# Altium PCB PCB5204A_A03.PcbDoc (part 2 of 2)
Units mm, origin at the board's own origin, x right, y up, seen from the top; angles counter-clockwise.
Board outline 38.5 x 55.5 mm, 4 copper layers (Top Layer, Signal Layer 2, Signal Layer 3, Bottom Layer), stack 1.6 mm thick; 164 components, 105 nets, 579 pads, 390 vias.
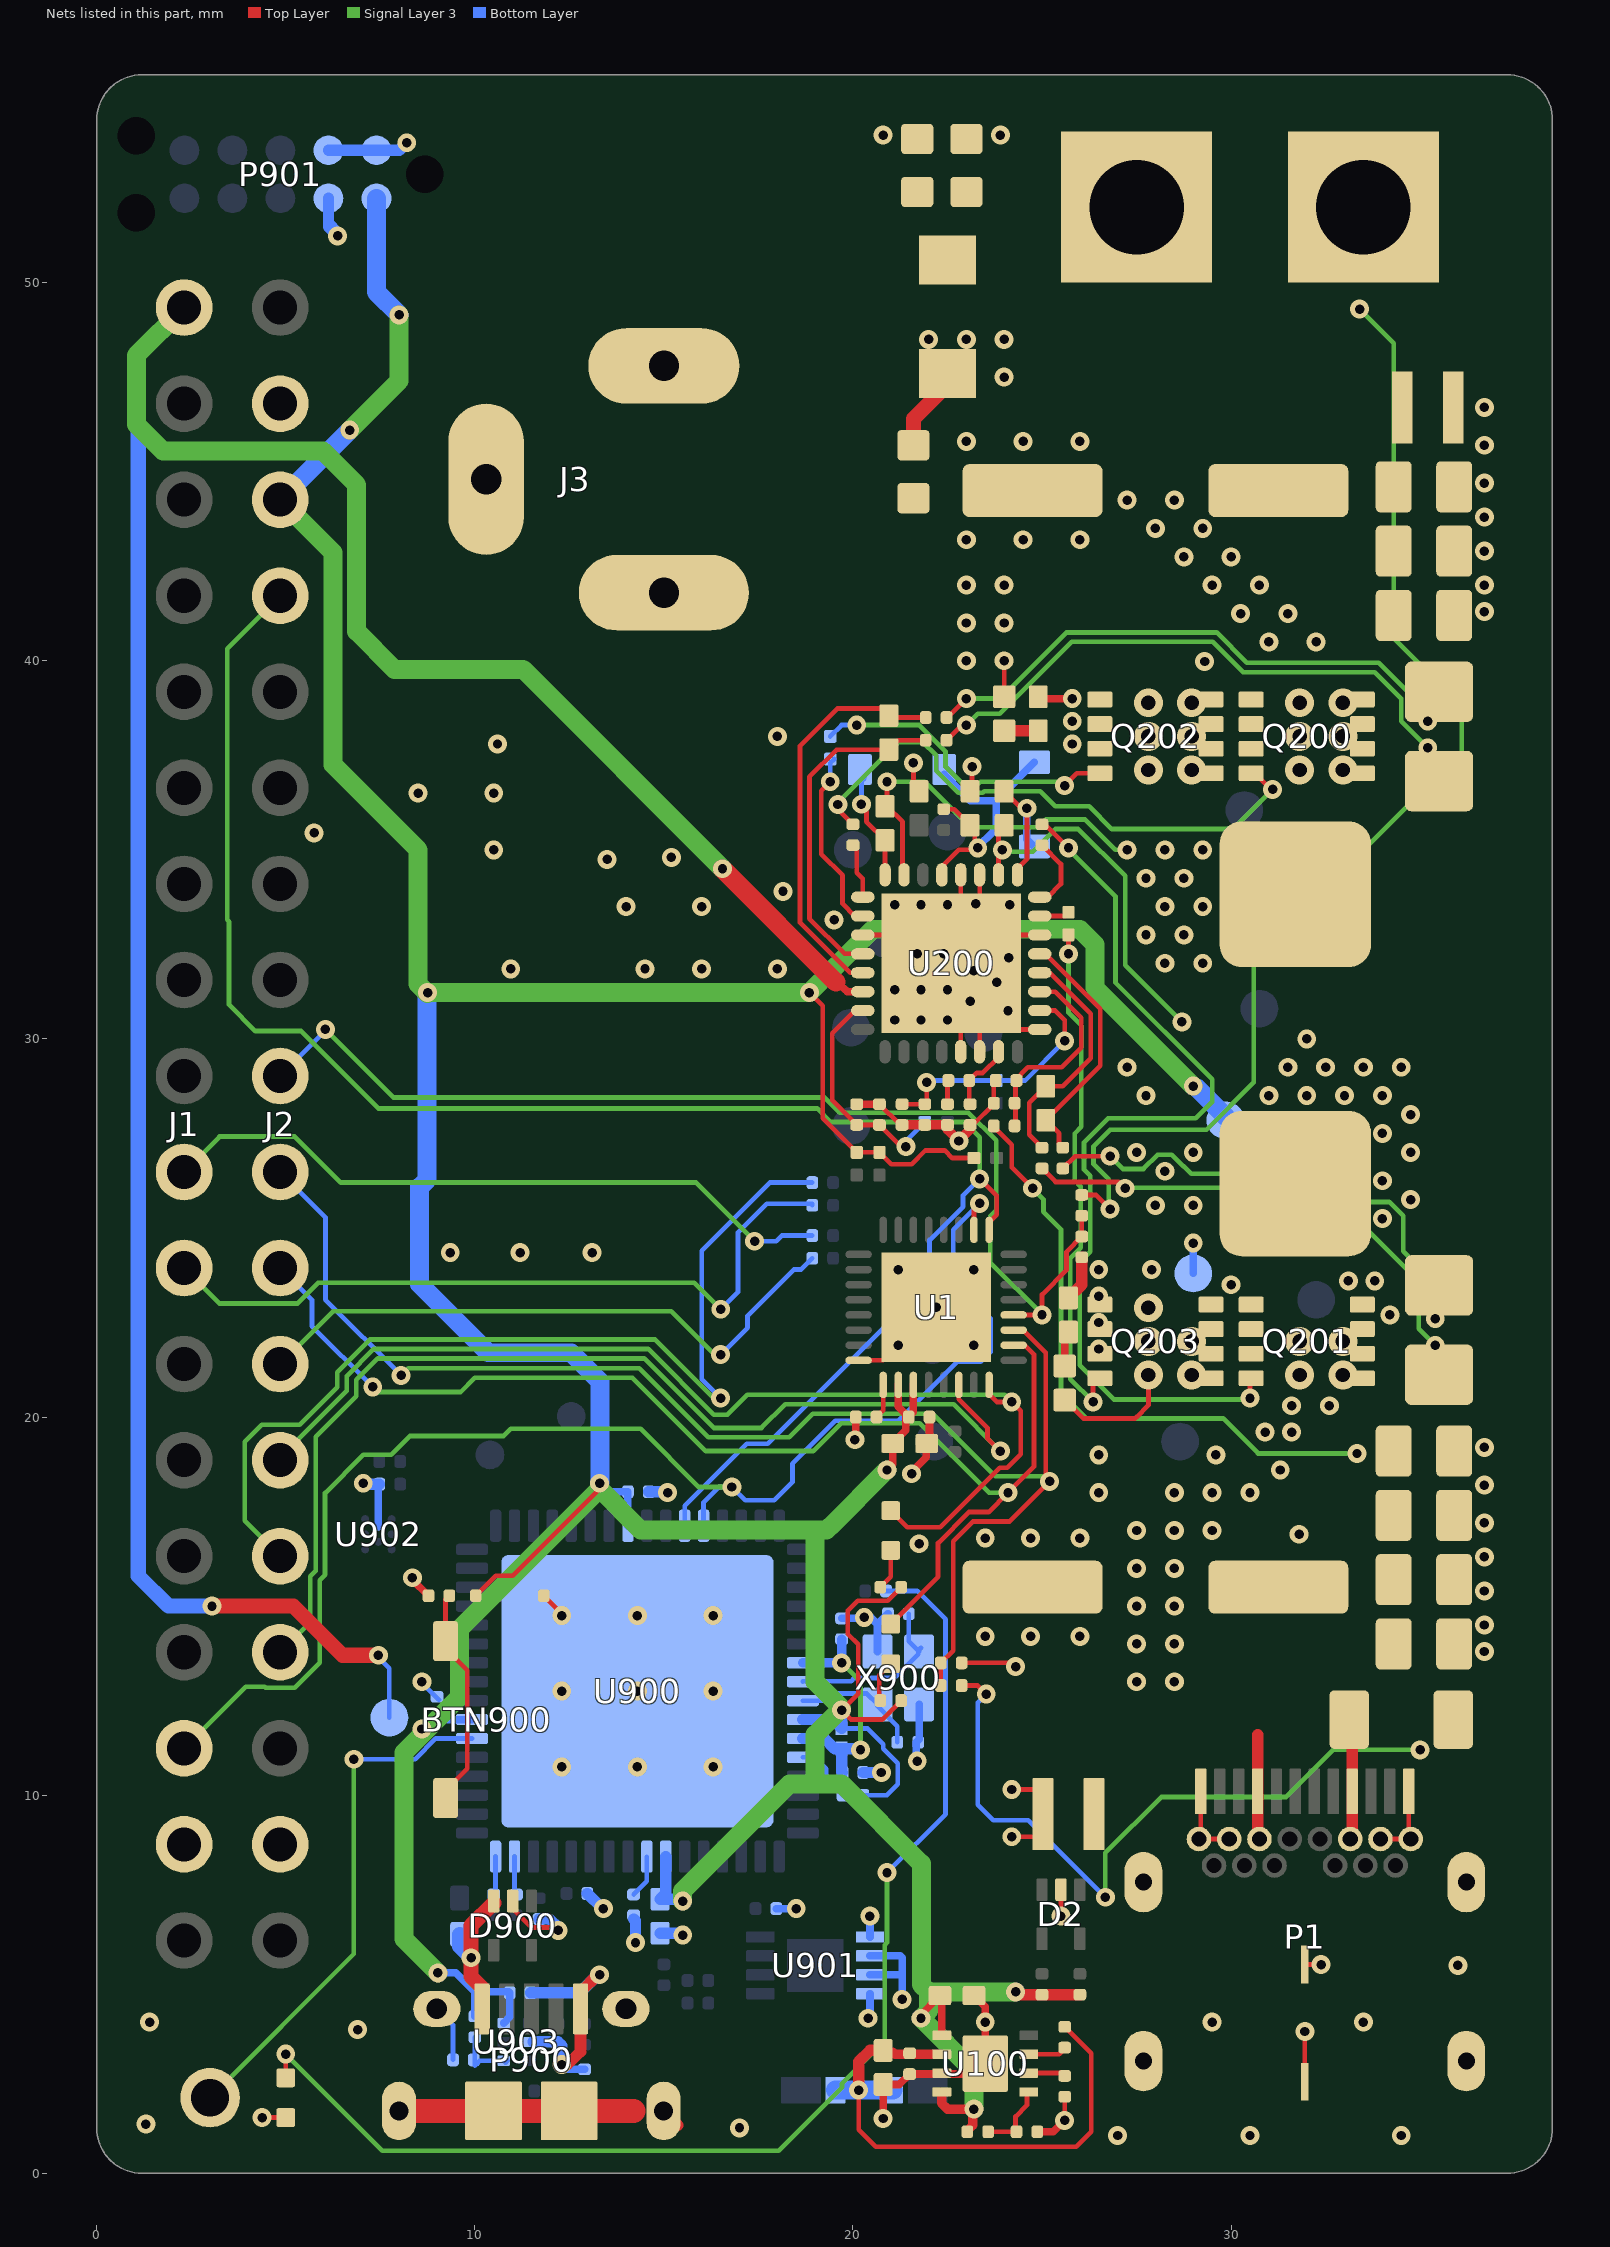
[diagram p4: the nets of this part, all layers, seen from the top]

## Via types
v1: diameter 0.5, hole 0.25, Top Layer to Bottom Layer, tented both sides, 369 vias
v2: diameter 0.762, hole 0.381, Top Layer to Bottom Layer, tented both sides, 21 vias

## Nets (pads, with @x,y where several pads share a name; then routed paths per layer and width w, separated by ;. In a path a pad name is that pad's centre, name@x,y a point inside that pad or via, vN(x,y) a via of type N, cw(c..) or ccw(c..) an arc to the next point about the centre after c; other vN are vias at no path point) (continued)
EFM8_P2.5: J2.9 R1.2 R2.2 U1.12 | length 29.9
  Top Layer w0.125: U1.12@24.25,22.7 24.975,22.7 v1@25,22.725 ; v1(25,22.7) v1@25,22.725 ; R1.2@26.05,25.325 R2.2@26.05,24.775 25.65,24.375 25.65,23.89 25,23.24 v1@25,22.725
  Signal Layer 3 w0.125: J2.9@4.853,29.02 J2.9@4.973,28.9 ; v1(6.05,30.25) 7.85,28.45 19.25,28.45 19.65,28.05 23.054,28.05 23.788,27.316 23.788,25.469 23.634,25.316 23.634,24.084 25,22.719 v1(25,22.7)
  Bottom Layer w0.125: J2.9@4.853,29.02 6.05,30.217 v1(6.05,30.25)
EFM8_P2.6: J2.10 R3.1 R4.2 U1.11 | length 37.4
  Top Layer w0.125: R3.1@22.325,12.9 R4.2@22.325,13.5 22.65,13.825 22.65,16.715 23.172,17.238 24.138,17.238 v1(25.2,18.3) 25.1,18.4 25.1,21.707 24.507,22.3 U1.11@24.25,22.3
  Signal Layer 3 w0.125: v1(8.05,21.1) 8.238,21.288 14.35,21.288 16.175,19.462 18.312,19.462 18.938,20.088 22.112,20.088 23.763,18.438 25.062,18.438 v1(25.2,18.3)
  Bottom Layer w0.125: J2.10@4.853,26.48 6.05,25.283 6.05,23.1 v1(8.05,21.1)
EFM8_P3.0: J2.11 LED100.1 U1.10 | length 32.7
  Top Layer w0.125: LED100.1@21,14.525 22.25,15.775 22.25,16.669 23.069,17.488 23.588,17.488 v1(24.1,18) 24.788,18.688 24.788,21.659 24.546,21.9 U1.10@24.25,21.9
  Signal Layer 3 w0.125: v1(7.3,20.8) 7.438,20.662 9.625,20.662 10,21.038 14.17,21.038 16.107,19.1 18.95,19.1 19.688,19.838 21.762,19.838 23.6,18 v1(24.1,18)
  Bottom Layer w0.125: J2.11@4.853,23.94 5.693,23.1 5.693,22.407 v1(7.3,20.8)
EFM8_P3.2: J2.13 LED101.1 U1.8 | length 28.7
  Top Layer w0.125: LED101.1@21,17.525 21.437,17.088 22.31,17.088 23.885,18.662 24.081,18.662 24.438,19.019 24.438,20.162 v1(24.2,20.4) 23.8,20.4 23.6,20.6 U1.8@23.6,20.85
  Signal Layer 3 w0.125: J2.13@4.853,18.86 4.853,18.931 6.612,20.69 6.612,21.085 7.328,21.8 14.581,21.8 16.319,20.062 16.681,20.062 17.206,20.588 24.012,20.588 v1(24.2,20.4)
EFM8_P3.4: J2.15 U1.6 | length 29
  Top Layer w0.125: U1.6@22.8,20.85 22.8,20.475 23.558,19.718 23.558,19.442 v1(23.9,19.1)
  Signal Layer 3 w0.125: J2.15@4.853,13.78 5.65,14.577 5.65,15.791 5.791,15.932 5.791,19.478 6.862,20.55 6.862,20.981 7.431,21.55 14.478,21.55 16.315,19.712 17.581,19.712 18.206,20.338 22.662,20.338 v1(23.9,19.1)
GND: C1.2 C2.2 C3.2 C100.2 C101.2 C102.2 C103.2 C200.2 C201.2 C202.2 C203.2 C204.2 C205.2 C206.2 C207.2 C208.2 C213.2 C214.2 C215.1 C216.1 C217.2 C218.2 C219.2 C220.2 C221.2 C222.2 C223.2 C900.2 C901.2 C902.2 C903.2 C904.2 C905.2 C906.2 C907.2 C908.2 C909.2 C910.2 C911.2 C912.2 C913.2 D1.2 D2.2 D3.2 D900.2 J1.17 J2.17 J3.2 J3.3 LED900.1 M2.1 P1.25 P1.26 P1.27 P1.28 P1.29 P1.30 P1.A1 P1.A12 P1.B1 P1.B12 P1.GND P900.5 P900.6 P900.7 P900.8 P900.9 P900.10 P900.11 P901.2 P901.9 P901.10 Q202.1 Q202.2 Q202.3 Q203.1 Q203.2 Q203.3 R2.1 R4.1 R102.2 R211.1 R212.1 R213.1 R214.1 R909.2 R911.2 R913.2 R914.1 TPJ13.1 U1.32 U1.33 U100.3 U100.9 U200.3 U200.13 U200.14 U200.17 U200.22 U200.27 U200.28 U200.33 U900.65 U901.1 U901.2 U901.3 U901.4 U902.B2 U903.2 X900.2 X900.4 | length 93.4
  Top Layer w0.125: v1(4.375,1.475) LED900.1@5,1.475 ; D900.2@11,7.2 11,7 11.5,6.5 12.2,6.5 12.207,6.493 v1(12.207,6.425) ; C913.2@11.825,15.275 12.3,14.8 v1(12.3,14.75) ; v1@13.25,5.25 v1(13.3,5.25) ; U1.32@20.15,21.5 20.8,21.5 v1(22.2,22.9) ; U200.3@20.26,32.75 21.4,32.75 U200.33@21.4,32.8 ; C217.2@20.7,28.275 21.25,27.725 C218.2@21.3,27.725 ; U200.33@21.1,33.5 U200.33@22.6,33.5 ; U200.33@21.147,32.775 U200.33@21.172,32.8 ; v1(21.6,37.3) 21.6,36.65 C215.1@21.7,36.55 ; U200.13@22.85,29.66 U200.33@22.85,31.5 ; U200.28@22.85,34.34 U200.33@22.85,33.34 ; R4.1@22.875,13.5 24.2,13.5 v1(24.3,13.4) ; C214.2@23.1,27.725 23.175,27.725 R212.1@23.737,28.287 ; C216.1@23.1,36.55 23.15,36.6 v1(23.15,37.2) ; v1(23.2,31.8) U200.33@22.9,31.8 ; U200.14@23.35,29.66 23.35,31.25 U200.33@23.1,31.5 ; U200.27@23.35,34.34 23.35,33.59 U200.33@24.1,33.59 ; R212.1@23.725,28.3 23.725,28.85 R211.1@23.775,28.9 ; U200.33@24.1,32 U200.33@23.35,32.75 ; U200.33@24.1,33.5 U200.33@23.395,32.795 ; U200.33@24.15,33.45 U200.33@24.15,33.54 ; U200.33@24.19,32 U200.33@24,32.19 ; v1(24.2,8.9) 24.85,8.9 D1.2@24.9,8.85 ; v1@24.25,10.15 D1.2@24.9,10.15 ; U200.17@24.94,30.25 23.9,30.25 23.9,31.29 23.69,31.5 U200.33@23.1,31.5 ; U200.22@24.94,32.75 24,32.75 U200.33@24,32.19 ; v1(25.5,6.8) D2.2@25.5,7.5 ; v1(25.6,1.4) C103.2@25.6,2.025 ; P1.A1@29.2,10.1 29.2,8.89 P1.B12@29.15,8.84 P1.GND@29.95,8.84 ; P1.30@31.95,2.42 v1(31.95,3.75) ; P1.29@31.95,5.52 v1(32.38,5.52) ; P1.GND@33.95,8.84 P1.B1@34.75,8.84 34.7,8.89 P1.A12@34.7,10.1 ; U200.33@21.172,32.8 U200.33@21.4,32.8 ; U200.33@21.172,32.8 21.4,33.028 U200.33@21.4,32.8 ; U200.33@21.4,32.8 21.6,32.6 22,32.6 22.3,32.3 22.4,32.3 v1(22.4,32.25) 22.4,32.2 U200.33@22.6,32 ; U200.33@22.6,32 22.6,31.75 U200.33@22.85,31.5 ; U200.33@22.6,32 U200.33@22.85,31.75 ; U200.33@22.6,32 U200.33@22.85,32.25 ; U200.33@22.6,33.5 22.69,33.5 U200.33@22.85,33.34 ; U200.33@22.6,33.5 U200.33@22.85,33.25 ; U200.33@22.85,31.5 U200.33@22.85,31.75 ; U200.33@22.85,31.5 U200.33@23.1,31.5 ; U200.33@22.85,31.75 U200.33@22.9,31.8 ; U200.33@22.85,32.25 U200.33@23.35,32.75 ; U200.33@22.85,32.25 U200.33@22.85,33.25 ; U200.33@22.85,33.25 U200.33@22.85,33.34 ; U200.33@22.85,33.25 U200.33@23.35,32.75 ; U200.33@22.85,33.34 U200.33@23.395,32.795 ; U200.33@22.9,31.8 22.9,31.7 U200.33@23.1,31.5 ; U200.33@23.35,32.75 U200.33@23.395,32.795 ; U200.33@23.395,32.795 U200.33@24,32.19
  Top Layer w0.2: v1(8.35,15.75) 8.35,15.7 R914.1@8.775,15.275 ; v1@20.075,19.475 C3.2@20.075,20 ; R213.1@20.1,28.275 C217.2@20.7,28.275 C217.2@20.711,28.275 ; C219.2@24.9,39.15 25.05,39 v1(25.8,39)
  Top Layer w0.203: v1(20.8,1.45) C100.2@20.8,2.35 21.225,2.35 C101.2@21.5,2.625 23.225,2.625 U100.9@23.5,2.9 v1@23.5,4.1 ; v1(21.55,18.5) 21.55,18.55 21.937,18.937 21.937,19.212 22.025,19.3 C2.2@22.025,20 ; C102.2@23.2,4.7 23.5,4.4 v1@23.5,4.1 ; v1(23.5,4) v1@23.5,4.1 ; R102.2@24.9,1.1 25.3,1.1 v1(25.6,1.4)
  Top Layer w0.254: C218.2@21.3,27.725 C213.2@22.5,27.725 22.5,27.6 v1(22.8,27.3) 23.1,27.6 C214.2@23.1,27.725
  Top Layer w0.3: P900.9@14.995,1.65 P900.9@15.37,1.275 ; C220.2@25.7,23.15 26.05,23.5 R2.1@26.05,24.225
  Top Layer w0.305: v1(12.3,2.875) 12.45,2.875 12.795,3.22 P900.5@12.795,4.35 12.795,4.795 v1@13.25,5.25
  Top Layer w0.635: P900.8@7.995,1.65 P900.10@10.495,1.65 P900.11@12.495,1.65 14.195,1.65
  Bottom Layer w0.125: v1(8.6,13) 8.6,12.975 C905.2@9.05,12.525 ; P900.6@8.995,4.35 9.425,3.92 R911.2@9.425,3
  Bottom Layer w0.2: U902.B2@7.45,17.1 C911.2@7.45,18.1 ; v1(12.3,2.875) 12.425,2.75 R909.2@12.9,2.75 ; TPJ13.1@29,23.8 v1(29,24.6)
  Bottom Layer w0.203: C910.2@17.975,7 v1(18.5,7) ; C909.2@19.7,14.675 20.275,14.675 v1(20.3,14.7) 20.475,14.7 20.65,14.525 ; v1(20.4,4.1) 20.45,4.15 U901.4@20.45,4.75 ; U901.3@20.45,5.25 21.25,5.25 21.3,5.2 ; U901.2@20.45,5.75 21.25,5.75 21.3,5.7 21.3,5.2 ; U901.1@20.45,6.25 v1(20.45,6.8) ; X900.2@20.65,13.8 20.65,14.525 ; C900.2@20.925,14.8 20.65,14.525 ; v1(21.3,4.6) 21.3,5.2 ; v1(21.7,10.9) 21.675,10.925 21.675,11.4 21.75,11.475 X900.4@21.75,12.4
  Bottom Layer w0.3: P901.2@6.13,52.23 6.13,51.571 ; P901.9@6.13,53.5 P901.10@7.4,53.5 8,53.5 v1(8.2,53.7) ; v1@7.05,18.225 C911.2@7.475,18.225 ; C912.2@11.475,4.775 12.775,4.775 13.25,5.25 v1(13.3,5.25) ; U903.2@11.538,3.475 12.2,3.475 12.3,3.375 v1(12.3,2.875) ; C904.2@11.7,6.725 11.975,6.725 12.207,6.493 v1(12.207,6.425) ; C903.2@12.975,7.4 13.375,7 v1(13.4,7) ; C902.2@14.2,6.725 14.25,6.675 v1(14.25,6.1) ; C906.2@14.6,18.025 15.075,18.025 v1(15.1,18) ; C907.2@14.9,6.35 15.45,6.35 v1(15.5,6.3) ; C908.2@20.275,10.6 v1(20.75,10.6) ; 6.13,51.571 6.13,51.477 v1(6.37,51.237) 6.37,51.33 6.13,51.571
  other v1: 27,1 30.5,1 34.5,1 17,1.2 1.3,1.3 6.9,3.8 1.4,4 29.5,4 33.5,4 36,5.5 24.2,10.15 12.3,10.75 14.3,10.75 16.3,10.75 12.3,12.75 14.3,12.75 16.3,12.75 36.7,13.8 23.5,14.2 24.7,14.2 26,14.2 36.7,14.5 14.3,14.75 16.3,14.75 36.7,15.4 36.7,16.3 21.75,16.65 23.5,16.8 24.7,16.8 26,16.8 36.7,17.2 36.7,18.2 7.05,18.25 36.7,19.2 20.05,19.4 26.5,21.8 21.2,21.9 23.2,21.9 26.5,22.5 26.5,23.2 21.2,23.9 23.2,23.9 26.5,23.9 9.35,24.35 11.2,24.35 13.1,24.35 21.1,30.5 21.8,30.5 22.5,30.5 24.1,30.75 23.1,31 21.1,31.3 21.8,31.3 22.5,31.3 23.8,31.5 10.95,31.85 14.5,31.85 16,31.85 18,31.85 24.125,32.15 21.7,32.25 19.5,33.15 14,33.5 16,33.5 21.1,33.55 21.8,33.55 22.5,33.55 24.15,33.55 23.25,33.575 18.15,33.9 13.5,34.75 15.2,34.8 10.5,35 5.75,35.45 8.5,36.5 10.5,36.5 10.6,37.8 25.8,37.8 18,38 25.8,38.4 36.7,41.3 36.7,42 36.7,42.9 23,43.2 24.5,43.2 26,43.2 36.7,43.8 36.7,44.7 36.7,45.7 23,45.8 24.5,45.8 26,45.8 36.7,46.7 20.8,53.9 23.9,53.9
N19125274: LED101.2 R104.1 | length 1.1
  Top Layer w0.125: R104.1@20.725,15.5 21,15.775 LED101.2@21,16.475
N19125276: LED100.2 R103.1 | length 1.1
  Top Layer w0.125: R103.1@20.695,12.53 20.695,13.17 LED100.2@21,13.475
N19280673: R903.1 U900.28 | length 1.6
  Bottom Layer w0.125: U900.28@18.675,11 18.988,11 19.288,10.7 19.288,10.437 R903.1@19.725,10
N19280703: C902.1 U900.40 | length 1.1
  Bottom Layer w0.125: C902.1@14.2,7.375 14.55,7.725 U900.40@14.55,8.375
N19280767: C908.1 C909.1 L901.2 U900.23 U900.27 | length 6.5
  Signal Layer 3 w0.125: v1(19.7,13.5) 20.2,13 v1(20.2,11.2)
  Bottom Layer w0.125: C908.1@19.725,10.6 C908.1@19.725,10.625
  Bottom Layer w0.254: U900.23@18.675,13.5 19.575,13.5 v1@19.7,13.625 ; v1(19.7,13.5) v1@19.7,13.625 ; C909.1@19.7,14.125 v1@19.7,13.625
  Bottom Layer w0.3: U900.27@18.675,11.5 19.245,11.5 19.515,11.23 L901.2@19.7,11.23 ; C908.1@19.725,10.6 19.7,10.625 L901.2@19.7,11.23 ; v1(20.2,11.2) 20.17,11.23 L901.2@19.7,11.23
N19280820: TP900.1 U900.54 | length 13.9
  Signal Layer 3 w0.125: TP900.1@3,2 6.8,5.8 v1(6.8,10.95)
  Bottom Layer w0.125: v1(6.8,10.95) 8.419,10.95 8.969,11.5 U900.54@9.925,11.5
N19280937: C900.1 U900.24 X900.3 | length 4.7
  Bottom Layer w0.127: U900.24@18.675,13 18.675,13.015 19.95,13.015 20.035,13.1 21.1,13.1 21.725,13.725 X900.3@21.725,13.825 ; C900.1@21.475,14.8 21.475,14.075 X900.3@21.725,13.825 ; X900.3@21.75,13.8 X900.3@21.725,13.825 ; X900.3@21.8,13.9 X900.3@21.725,13.825
N19280939: C901.1 U900.25 X900.1 | length 3.3
  Bottom Layer w0.125: U900.25@18.675,12.5 19.3,12.5 19.488,12.688 20.362,12.688 X900.1@20.65,12.4 ; X900.1@20.65,12.35 21.175,11.825 C901.1@21.175,11.4
N19281082: LED900.2 R902.2 | length 32.5
  Top Layer w0.125: LED900.2@5,2.525 v1(5,3.15)
  Signal Layer 3 w0.125: v1(5,3.15) 7.55,0.6 18.034,0.6 19.712,2.278 19.712,2.381 20.838,3.506 20.838,6.038 20.9,6.1 v1(20.9,7.95)
  Bottom Layer w0.125: R902.2@20.875,15.4 21.7,15.4 22.45,14.65 22.45,9.5 v1(20.9,7.95)
N19281102: R901.2 U900.48 | length 0.9
  Bottom Layer w0.127: R901.2@10.55,7.45 U900.48@10.55,8.375
N19281104: R900.2 U900.47 | length 0.9
  Bottom Layer w0.127: R900.2@11.05,7.45 U900.47@11.05,8.375
N19706111: C3.1 U1.1 | length 0.9
  Top Layer w0.125: C3.1@20.625,20 20.8,20.175 U1.1@20.8,20.85
N19776318: D900.3 L900.1 P900.1 | length 3.9
  Top Layer w0.4: P900.1@10.195,4.35 10.195,4.905 9.9,5.2 v1(9.9,5.7) 9.9,6.55 D900.3@10.5,7.15
  Bottom Layer w0.4: L900.1@9.6,6.32 9.6,6 v1(9.9,5.7)
N19777809: R910.2 R911.1 U903.4 | length 1.6
  Bottom Layer w0.127: R910.2@10,3.6 10,2.85 10.125,2.975 U903.4@10.763,2.975 ; U903.4@10.812,2.925 U903.4@10.863,2.975
N20015070: J2.14 R920.1 | length 25.8
  Signal Layer 3 w0.125: J2.14@4.853,16.32 3.915,17.258 3.915,19.345 4.368,19.798 5.366,19.798 6.362,20.794 6.362,21.188 7.224,22.05 14.774,22.05 16.324,20.5 v1(16.5,20.5)
  Bottom Layer w0.125: v1(16.5,20.5) 16,21 16,24.4 17.8,26.2 R920.1@18.925,26.2
N20015198: J2.12 R919.1 | length 16.4
  Signal Layer 3 w0.125: J2.12@4.853,21.4 6.253,22.8 6.914,22.8 ; 6.914,22.8 15.193,22.8 16.343,21.65 v1(16.5,21.65)
  Bottom Layer w0.125: v1(16.5,21.65) 17.213,22.363 17.213,22.681 18.431,23.9 18.625,23.9 R919.1@18.925,24.2
N20015887: J1.10 R917.1 | length 18.2
  Signal Layer 3 w0.125: J1.10@2.313,26.48 3.251,27.418 5.241,27.418 6.459,26.2 15.85,26.2 v1(17.4,24.65)
  Bottom Layer w0.125: v1(17.4,24.65) 17.969,24.65 18.119,24.8 R917.1@18.925,24.8
N20015953: J1.11 R918.1 | length 19.6
  Signal Layer 3 w0.125: J1.11@2.313,23.94 3.251,23.002 5.308,23.002 5.855,23.55 15.804,23.55 v1(16.504,22.85)
  Bottom Layer w0.125: v1(16.504,22.85) 16.962,23.309 16.962,24.881 17.719,25.638 18.925,25.638 R918.1@18.925,25.6
N20143215: C209.1 L200.1 Q200.1 Q200.2 Q200.3 Q202.5 Q202.6 Q202.7 Q202.8 R215.2 U200.31 | length 10.8
  Top Layer w0.125: v1(20.9,36.8) 20.9,36.15 21.312,35.738 21.312,34.378 U200.31@21.35,34.34 ; R215.2@24,39.15 v1(24,40)
  Signal Layer 3 w0.125: v1(20.9,36.8) 21.9,36.8 23.1,35.6 24.9,35.6 25.1,35.8 26.138,35.8 26.938,35 v1(27.25,35)
  other v1: 28.25,32 29.25,32 27.75,32.75 28.75,32.75 28.25,33.5 29.25,33.5 27.75,34.25 28.75,34.25 28.25,35 29.25,35 29.299,39.982 23,40 23,41 24,41 23,42 24,42
  other v2: 27.814,37.111 28.957,37.111 27.814,38 28.957,38 27.814,38.889 28.957,38.889
N20143229: Q200.5 Q200.6 Q200.7 Q200.8 R200.2 R205.2 | length 15.3
  Top Layer w0.125: R205.2@22.475,37.9 22.875,38.3 v1(23,38.3)
  Signal Layer 3 w0.125: v1(23,38.3) 23.3,38.6 23.883,38.6 25.783,40.5 29.517,40.5 30.317,39.7 33.8,39.7 34.5,39 34.5,38.4 v1(35.2,37.7)
  other v1: 31,40.5 32.25,40.5 30.25,41.25 31.5,41.25 29.5,42 30.75,42 28.75,42.75 30,42.75 28,43.5 29.25,43.5 27.25,44.25 28.5,44.25
  other v2: 31.814,37.111 32.957,37.111 31.814,38 32.957,38 31.814,38.889 32.957,38.889
N20143236: C210.1 L200.2 Q201.1 Q201.2 Q201.3 Q203.5 Q203.6 Q203.7 Q203.8 R216.2 U200.26 | length 13.5
  Top Layer w0.125: U200.26@23.85,34.34 23.85,35.45 23.8,35.5 C210.1@24,35.7 ; R216.2@25.6,20.45 26.088,19.962 27.462,19.962 27.5,20 27.814,20.314 v2(27.814,21.111)
  Signal Layer 3 w0.125: v1@23.85,34.95 24.75,34.95 25.35,35.55 25.96,35.55 27.2,34.31 27.2,31.95 v1(28.7,30.45)
  Bottom Layer w0.125: v2@27.711,21.111 v2(27.814,21.111)
  other v1: 30,23.5 27.9,23.9 34,25.25 28,25.6 29,25.6 34.75,25.75 34,26.25 28.25,26.5 27.5,27 29,27 34.75,27 34,27.5 34.75,28 27.75,28.5 31,28.5 32,28.5 33,28.5 34,28.5 27.25,29.25 31.5,29.25 32.5,29.25 33.5,29.25 34.5,29.25 32,30 23.95,35
  other v2: 28.957,21.111 27.814,22 28.957,22 27.814,22.889
N20143250: Q202.4 R217.2 | length 8.3
  Top Layer w0.125: v1(25.6,36.7) 25.925,37.025 Q202.4@26.53,37.025
  Signal Layer 3 w0.125: v1(20.1,38.3) 21.75,38.3 22.45,37.6 22.45,37.2 22.888,36.762 23.331,36.762 23.369,36.8 25.5,36.8 v1(25.6,36.7)
  Bottom Layer w0.125: R217.2@19.4,38 19.7,38.3 v1(20.1,38.3)
N20143259: Q200.4 R202.2 | length 15.4
  Top Layer w0.125: v1@19.6,36.175 19.6,36.075 R202.2@20,35.675 ; Q200.4@30.53,37.025 30.62,37.025 31.1,36.545 v1(31.1,36.6)
  Signal Layer 3 w0.125: v1(19.6,36.2) 19.6,36.25 21.2,37.85 21.846,37.85 22.2,37.496 22.2,37.096 22.784,36.512 23.435,36.512 23.472,36.55 24.95,36.55 25.35,36.15 26.25,36.15 26.85,35.55 30.05,35.55 v1(31.1,36.6)
N20143264: R203.1 U200.24 | length 1.9
  Top Layer w0.125: U200.24@24.94,33.75 25.15,33.75 25.5,34.1 25.5,34.625 R203.1@25,35.125
N20143267: C204.1 C205.1 C206.1 C207.1 C208.1 L201.1 R3.2 R201.2 R207.2 R210.2 | length 48.4
  Top Layer w0.125: R3.2@22.875,12.9 23.3,12.9 v1(23.525,12.675) ; R210.2@23.725,27.7 23.725,27.675 24.2,27.2 24.2,26.6 v1(24.75,26.05) ; v1@24.775,26.075 v1@24.9,25.95 ; R207.2@25,26.575 25.357,26.218 27.032,26.218 v1(27.2,26.05)
  Signal Layer 3 w0.125: v1(24.75,26.05) 25.038,25.762 25.038,25.431 25.5,24.969 25.5,20.631 26.169,19.962 29.788,19.962 30.712,19.038 33.329,19.038 v1(33.33,19.037) ; v1(26.675,7.3) 26.675,8.473 28.152,9.95 31.45,9.95 32.7,11.2 v1(35,11.2) ; v1@27.2,25.931 v1(27.2,26.05) 27.212,26.062 32.488,26.062 34.962,23.588 34.962,22.338 v1(35.4,21.9)
  Bottom Layer w0.125: v1(23.525,12.675) 23.3,12.45 23.3,9.75 23.713,9.337 24.637,9.337 v1(26.675,7.3)
N20143311: Q201.5 Q201.6 Q201.7 Q201.8 R201.1 R206.2 | length 13.2
  Top Layer w0.125: R206.2@25.55,26.575 25.875,26.9 v1(26.8,26.9)
  Signal Layer 3 w0.125: v1(26.8,26.9) 27.137,26.562 27.681,26.562 28.056,26.938 28.431,26.938 28.75,26.618 ; 28.757,26.625 28.944,26.438 32.466,26.438 33.216,25.688 34.181,25.688 34.55,25.319 34.55,24.384 35.4,23.534 v1(35.4,22.6)
  other v1: 27.5,13 28.5,13 27.5,14 28.5,14 27.5,15 28.5,15 27.5,16 28.5,16 31.8,16.9 27.5,17 28.5,17 29.5,17 26.5,18 28.5,18 29.5,18 30.5,18 31.3,18.6 26.5,19 29.6,19 30.9,19.6 31.6,19.6 31.6,20.3 32.6,20.3 34.2,22.7 33.1,23.6 33.8,23.6
  other v2: 31.814,21.111 32.957,21.111 31.814,22 32.957,22
N20143319: C211.1 R204.1 U200.5 | length 10.9
  Top Layer w0.125: U200.5@20.26,31.75 19.928,31.75 18.6,33.078 18.6,37.75 19.588,38.738 20.95,38.738 C211.1@20.95,38.55 20.9,38.5 R204.1@21.925,38.5
N20143320: C211.2 R205.1 U200.4 | length 9
  Top Layer w0.125: U200.4@20.26,32.25 19.781,32.25 18.85,33.181 18.85,36.933 19.567,37.65 C211.2@20.95,37.65 21.2,37.9 R205.1@21.925,37.9
N20143323: C212.1 R206.1 U200.21 | length 6.7
  Top Layer w0.125: U200.21@24.94,32.25 25.081,32.25 26.537,30.794 26.537,29.287 C212.1@25.1,27.85 25.45,27.5 25.45,27.225 R206.1@25.55,27.125
N20143325: C212.2 R207.1 U200.20 | length 6.4
  Top Layer w0.125: U200.20@24.94,31.75 25.204,31.75 26.287,30.666 26.287,29.491 25.546,28.75 C212.2@25.1,28.75 24.662,28.312 24.662,27.463 R207.1@25,27.125
N20143355: R202.1 U200.1 | length 1.4
  Top Layer w0.125: R202.1@20.1,35.125 20.1,34.4 20.26,34.24 U200.1@20.26,33.75
N20143401: R210.1 R211.2 R212.2 U200.19 | length 5.5
  Top Layer w0.125: R211.2@24.275,28.9 24.625,29.25 25.519,29.25 26.037,29.769 26.037,30.563 25.35,31.25 U200.19@24.94,31.25 ; R210.1@24.3,27.7 24.3,28.9 R211.2@24.317,28.883
N20143431: C210.2 D201.1 U200.25 | length 3.8
  Top Layer w0.125: C210.2@24,36.55 v1@24.45,36.1 ; U200.25@24.35,34.34 24.35,34.5 24.6,34.75 24.6,36.048 24.502,36.048 v1@24.45,36.1 ; v1(24.6,36.1) v1@24.45,36.1
  Bottom Layer w0.2: v1@24.6,36.048 24.6,35.285 D201.1@24.8,35.085
N20143434: Q203.4 R218.2 | length 13.7
  Top Layer w0.125: v1@25.7,32.2 v1(25.7,32.25) R218.2@25.7,32.75 ; v1(26.35,20.4) 26.35,20.845 Q203.4@26.53,21.025
  Signal Layer 3 w0.125: v1@25.7,32.2 25.7,30.7 26.037,30.363 26.037,27.674 25.862,27.499 25.862,26.259 26.025,26.096 26.025,24.479 25.75,24.204 25.75,21 v1(26.35,20.4)
N20147822: C209.2 D200.1 U200.32 | length 2.8
  Top Layer w0.125: v1@20.2,36.2 20.2,36.175 20.358,36.018 20.358,35.742 C209.2@20.85,35.25 ; U200.32@20.85,34.34 20.85,35.2 C209.2@20.875,35.225
  Bottom Layer w0.125: v1(20.225,36.205) 20.225,36.81 D200.1@20.3,36.885
N20159251: C214.1 R208.1 U200.15 | length 1.8
  Top Layer w0.125: C214.1@23.1,28.275 23.075,28.3 R208.1@23.075,28.9 23.275,29.1 23.432,29.1 23.85,29.518 U200.15@23.85,29.66
N20159257: C213.1 R208.2 | length 0.6
  Top Layer w0.125: C213.1@22.5,28.275 22.5,28.875 R208.2@22.525,28.9
N20160223: C217.1 R213.2 R222.2 U200.7 | length 6.1
  Top Layer w0.125: U200.7@20.26,30.75 20.05,30.75 19.45,30.15 19.45,28.375 R213.2@20.1,27.725 C217.1@20.7,27.725 21.275,27.15 v1(21.4,27.15)
  Bottom Layer w0.125: v1@21.4,27.201 21.4,27.3 R222.2@21.9,27.8
N20160239: C218.1 R214.2 R223.2 U200.18 | length 6.5
  Top Layer w0.125: C218.1@21.3,28.275 R214.2@21.9,28.275 21.95,28.325 v1(21.95,28.85) ; U200.18@24.94,30.75 25.35,30.75 25.6,30.5 v1(25.6,29.95)
  Bottom Layer w0.125: v1@22,28.9 24.55,28.9 v1(25.6,29.95)
N20232000: C103.1 U100.6 | length 1
  Top Layer w0.127: U100.6@24.65,2.65 25.55,2.65 C103.1@25.6,2.6
N20232022: R101.2 R102.1 U100.5 | length 1.8
  Top Layer w0.127: R101.2@23.6,1.1 24.3,1.1 24.3,1.5 24.6,1.8 U100.5@24.6,2.1
N20232024: C100.1 C101.1 D901.1 D902.1 R100.1 U100.2 | length 15
  Top Layer w0.125: v1(20.15,2.2) 20.15,1.15 20.6,0.7 25.9,0.7 26.3,1.1 26.3,3.175 R100.1@25.6,3.875
  Top Layer w0.25: 21.05,3.2 21.1,3.15 U100.2@22.35,3.15
  Top Layer w0.3: v1(20.15,2.2) 20.15,2.95 20.45,3.25 C100.1@20.8,3.25
  Bottom Layer w0.5: D902.1@19.54,2.2 v1(20.15,2.2) D901.1@21.06,2.2
N20232193: R100.2 U100.7 | length 1
  Top Layer w0.127: U100.7@24.65,3.15 25.45,3.15 R100.2@25.6,3.3
N20240329: BTN900.3 BTN900.4 R914.2 | length 5.9
  Top Layer w0.125: BTN900.4@9.225,9.925 9.225,10.125 9.8,10.7 9.8,13.3 9.225,13.875 BTN900.3@9.225,14.075 9.225,15.175 R914.2@9.325,15.275
N20265075: C219.1 R215.1 | length 0.9
  Top Layer w0.3: R215.1@24,38.15 C219.1@24.9,38.15
N20265147: C220.1 R216.1 | length 0.9
  Top Layer w0.2: R216.1@25.6,21.35 25.6,22.15 C220.1@25.7,22.25
N20274785: R217.1 U200.2 | length 4.9
  Top Layer w0.125: v1(19.4,36.8) 19.162,36.562 19.162,34.888 19.725,34.325 19.725,33.575 20.05,33.25 U200.2@20.26,33.25
  Bottom Layer w0.125: v1(19.4,36.8) 19.4,37.3 R217.1@19.5,37.4
N20276563: R218.1 U200.23 | length 0.8
  Top Layer w0.125: U200.23@24.94,33.25 25.6,33.25 R218.1@25.7,33.35
N20297522: C221.1 C222.1 J3.1 L202.1 M1.1
N201435831: Q201.4 R203.2 | length 24.6
  Top Layer w0.125: R203.2@25,35.675 25.075,35.675 v1(25.7,35.05) ; v1(30.5,20.5) 30.5,20.995 Q201.4@30.53,21.025
  Signal Layer 3 w0.125: v1(25.7,35.05) 25.7,35.017 26.942,33.775 26.942,31.492 29.5,28.934 29.5,28.334 29.066,27.9 26.746,27.9 26.112,27.266 26.112,26.538 26.275,26.375 26.275,24.375 26,24.1 26,21.369 26.906,20.462 30.462,20.462 v1(30.5,20.5)
USBC_VBUS: D1.1 J2.2 L201.2 P1.A4 P1.A9 P1.B4 P1.B9 | length 5.7
  Top Layer w0.305: 30.7,11.6 P1.A4@30.7,10.1 30.7,8.89 P1.B9@30.75,8.84 ; P1.B4@33.15,8.84 33.2,8.89 P1.A9@33.2,10.1 L201.2@33.2,11.7
VCOM_RX: J2.4 U1.17 U900.11 | length 48.2
  Top Layer w0.125: v1(23.35,26.3) 23.8,25.85 23.8,25.35 23.6,25.15 U1.17@23.6,24.95
  Signal Layer 3 w0.125: J2.4@4.853,41.72 3.45,40.317 3.45,33.151 3.501,33.1 3.501,30.903 4.196,30.208 5.404,30.208 7.449,28.162 19.05,28.162 19.412,27.8 22.95,27.8 23.35,27.4 v1(23.35,26.3)
  Bottom Layer w0.125: U900.11@15.55,17.125 15.55,17.65 17.197,19.297 17.749,19.297 22.026,23.574 22.026,24.679 22.912,25.566 22.912,25.862 v1(23.35,26.3)
VCOM_TX: J1.16 U1.18 U900.12 | length 37
  Top Layer w0.125: U1.18@23.2,24.95 23.2,25.525 23.3,25.625 v1@23.325,25.625
  Signal Layer 3 w0.125: J1.16@2.313,11.24 3.939,12.866 4.441,12.866 4.465,12.842 5.241,12.842 5.9,13.501 5.9,15.688 6.041,15.828 6.041,17.991 7.05,19 7.787,19 8.287,19.5 10.763,19.5 10.95,19.688 14.385,19.688 15.922,18.15 v1(16.8,18.15)
  Bottom Layer w0.125: U900.12@16.05,17.125 16.05,17.75 16.45,18.15 v1(16.8,18.15) 17.15,17.8 17.919,17.8 18.4,18.281 18.4,18.766 19.534,19.9 21.2,19.9 22.762,21.462 23.381,21.462 23.638,21.719 23.638,22.612 22.65,23.6 22.65,24.95 v1@23.325,25.625
  other v1: 23.35,25.65
VDD: C1.1 C2.1 C102.1 C905.1 C906.1 C907.1 C912.1 J2.3 L901.1 P901.1 R13.2 R21.2 R101.1 R103.2 R104.2 R219.1 R220.1 R221.1 R903.2 R910.1 R915.1 TPJ10.1 U1.2 U1.3 U100.1 U100.4 U900.8 U900.26 U900.39 U900.55 U903.6 | length 156
  Top Layer w0.125: R915.1@10.025,15.275 10.55,15.8 11,15.8 v1@13.3,18.1 ; v1(18.85,31.225) 19.2,30.875 19.2,27.9 R219.1@20.1,27 R220.1@20.7,27 21.012,26.688 21.556,26.688 21.919,27.05 22.431,27.05 22.631,26.85 R221.1@23.15,26.85 ; R103.2@21.275,12.5 20.775,12 19.95,12 v1(19.7,12.25) 20.138,12.688 20.138,13.987 19.862,14.262 19.862,14.881 20.124,15.142 20.917,15.142 R104.2@21.275,15.5
  Top Layer w0.2: v1@21.05,18.75 C1.1@21.05,19.3 21.4,19.65 C2.1@21.4,20 ; U1.2@21.2,20.85 21.2,20.275 C2.1@21.475,20 21.6,20.125 U1.3@21.6,20.85 ; v1(21.8,4.1) 21.8,4.2 C102.1@22.25,4.65 ; C102.1@22.3,4.7 C102.1@22.25,4.65 ; U100.1@22.35,3.65 22.35,4.65 C102.1@22.25,4.65
  Top Layer w0.25: U100.4@22.35,2.15 22.35,1.85 22.5,1.7 v1(23.2,1.7) 23.17,1.67 23.17,1.27 23.025,1.125 R101.1@23.025,1.1
  Top Layer w0.305: v1(24.3,4.8) 24.375,4.725 R13.2@25,4.725 R21.2@26,4.725
  Signal Layer 3 w0.5: J2.3@4.853,44.26 6.25,42.863 6.25,37.25 8.5,35 8.5,31.45 8.75,31.2 8.775,31.225 v1(18.85,31.225) 20.525,32.9 26,32.9 26.4,32.5 26.4,31.35 v1(29,28.75) ; v1(6.693,46.1) 8,47.407 v1(8,49.15) ; v1(9.025,5.3) 8.125,6.2 8.125,11.125 9.6,12.6 9.6,14.4 13.3,18.1 14.387,17.012 18.95,17.012 ; v1@15.495,7.205 15.495,7.47 18.326,10.3 19,10.3 ; v1@19.675,12.275 19,11.6 19,10.3 ; v1@19.7,12.3 19,13 19,16.962 18.95,17.012 ; v1(20.9,18.6) 19.4,17.1 19.384,17.1 19.297,17.012 18.95,17.012 ; v1(23.2,1.7) 23.2,2.7 v1(21.8,4.1) 22,4.3 22,4.8 ; v1(24.3,4.8) 22,4.8 ; 19,10.3 19.7,10.3 21.81,8.19 21.81,4.99 22,4.8
  Bottom Layer w0.125: L901.1@19.7,11.77 19.708,11.762 20.388,11.762 20.8,11.35 20.8,11.232 21.188,10.845 21.188,10.288 20.9,10 R903.2@20.275,10
  Bottom Layer w0.2: v1(8.6,11.75) 8.9,12.05 C905.1@9,12.05 ; C905.1@9,12 U900.55@9.925,12 ; v1(9.025,5.3) 9.5,5.3 10,4.8 ; R910.1@10,4.15 10,4.8 ; U903.6@10.763,3.975 10.925,4.137 C912.1@10.925,4.775 10.9,4.8 10,4.8 ; v1(13.3,18.25) 13.525,18.025 C906.1@14.05,18.025 U900.8@14.05,17.125
  Bottom Layer w0.3: U900.26@18.675,12 19.47,12 L901.1@19.7,11.77 v1(19.7,12.25)
  Bottom Layer w0.305: U900.39@15.05,8.375 15.05,7.4 C907.1@14.9,7.25 15.45,7.25 v1(15.5,7.2)
  Bottom Layer w0.5: J2.3@4.853,44.26 v1(6.693,46.1) ; P901.1@7.4,52.23 7.4,49.75 v1(8,49.15) ; v1@8.738,31.2 8.738,26.282 8.537,26.082 8.537,23.513 10.35,21.7 12.55,21.7 13.316,20.934 13.316,18.266 v1(13.3,18.25) ; v1@29.1,28.7 TPJ10.1@29.85,27.95
  other v1: 8.75,31.225
VDRV: C216.2 D200.2 D201.2 R209.1 U200.29 | length 7.5
  Top Layer w0.125: U200.29@22.35,34.34 22.35,34.55 22.8,35 23.222,35 23.222,35.528 C216.2@23.1,35.65 22.675,36.075 R209.1@22.4,36.075
  Bottom Layer w0.2: D200.2@22.415,37 22.415,36.985 23.1,36.3 23.785,36.3 ; v1@23.222,35 23.785,35.563 23.785,36.3 ; D201.2@24.8,37.315 23.785,36.3
  other v1: 23.3,35.05
VIN: C200.1 C201.1 C202.1 C203.1 C223.1 D3.1 J1.1 L202.2 R1.1 R200.1 R204.2 TPJ20.1 U200.6 | length 122.9
  Top Layer w0.125: R204.2@22.5,38.5 v1(23,39) ; R1.1@26,25.875 R1.1@26.05,25.875 26.425,25.875 v1(26.8,25.5) ; v1(33.4,49.3) v1@33.5,49.2
  Top Layer w0.2: 19.55,31.5 19.85,31.25 U200.6@20.26,31.25
  Top Layer w0.4: v1@3.1,15 5.2,15 6.5,13.7 v1(7.45,13.7) ; C223.1@21.6,45.7 21.6,46.4 L202.2@22.5,47.3
  Top Layer w0.5: v1(16.55,34.5) 19.55,31.5
  Signal Layer 3 w0.125: v1(23,39) 23.9,39 25.65,40.75 29.621,40.75 30.421,39.95 33.904,39.95 35.2,38.654 v1(35.2,38.4) ; v1@26.734,25.5 v1(26.8,25.5) 26.762,25.538 26.762,26.288 26.362,26.688 26.362,27.162 26.8,27.6 29.35,27.6 30.6,28.85 30.6,32.1 36.1,37.6 36.1,38.8 34.3,40.6 34.3,48.4 v1(33.4,49.3)
  Signal Layer 3 w0.5: J1.1@2.313,49.34 1.05,48.077 1.05,46.25 1.75,45.55 5.978,45.55 6.875,44.653 6.875,40.775 7.875,39.775 11.275,39.775 v1(16.55,34.5)
  Bottom Layer w0.125: J1.1@2.313,49.34 J1.1@2.313,49.413 ; v1(7.45,13.7) 7.45,13.65 7.74,13.36 TPJ20.1@7.74,12.05
  Bottom Layer w0.4: J1.1@2.313,49.34 1.1,48.127 1.1,15.8 1.9,15 v1(3.05,15) v1@3.1,15
  other v1: 24,47.5 22,48.5 23,48.5 24,48.5
pads on no net: D2.1 D2.3 D900.1 J1.2 J2.16 P1.0 P1.A2 P1.A3 P1.A6 P1.A7 P1.A8 P1.A10 P1.A11 P1.B2 P1.B3 P1.B6 P1.B7 P1.B8 P1.B10 P1.B11 P900.4 P901.M1 P901.M2 P901.M3 TPJ4.1 TPJ7.1 TPJ8.1 TPJ9.1 TPJ18.1 TPJ19.1 U100.8 U200.8 U200.12 U200.16 U900.3 U900.5 U900.6 U900.9 U900.10 U900.13 U900.14 U900.15 U900.16 U900.17 U900.18 U900.19 U900.22 U900.29 U900.30 U900.31 U900.33 U900.34 U900.35 U900.42 U900.43 U900.44 U900.53 U900.56 U900.57 U900.64 U901.9 U902.C1 U903.5

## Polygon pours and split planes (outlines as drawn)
GND on Signal Layer 2 "GND_L2" (solid, remove dead copper, pour order 21): 0,0 0,56 38.5,56 38.5,0
N20143215 on Signal Layer 3 "Q202_L3" (solid, remove dead copper, pour order 16): 26.5,36.3 26.5,29.8 30.4,29.8 30.4,31.5 35.2,36.3 30.7,36.3 24.6,42.4 12.9,42.4 12.9,39.2 23.4,39.2
GND on Signal Layer 3 "GND_L3" (solid, remove dead copper, pour order 22): 0,0 0,56 37.5,56 37.5,0
N20143236 on Signal Layer 3 "Q203_L3" (solid, remove dead copper, pour order 14): 27,29.7 30.5,29.7 30.5,31.5 36,37 36,24.5 32,24.5 30.5,23 27,23
N20143311 on Signal Layer 3 "Q201_L3" (solid, remove dead copper, pour order 15): 32,24 30.5,22.5 27,22.5 27,20.545 25,18.545 25,10 37,10 37,24
USBC_VBUS on Signal Layer 3 "Vbus_L3" (solid, remove dead copper, pour order 19): 30,10 30,9 30.5,8.5 37,8.5 38.2,9.7 38.2,55.5 7.5,55.5 3.5,51.5 3.5,46.5 4,46 5.5,46 7.5,48 7.5,50.5 9.5,52.5 34.5,52.5 34.5,47.5 34.5,13 31.5,10
VIN on Signal Layer 3 "VIN_L3" (solid, remove dead copper, pour order 20): 25,52.5 10,52.5 8,50.5 8,48.5 5.5,46 3,46 3,51 1,51 0.5,51 0.5,42.5 9.5,42.5 9.5,47.175 12.225,47.175 13.4,48.35 16.575,48.35 17.75,47.175 25,47.175
N20143311 on Bottom Layer "Q201_Bot" (solid, remove dead copper, pour order 12): 31.9,24.8 30.51,23.41 30.51,17.3 27.1,17.3 27.1,5 38.5,5 38.5,24.8
N20143229 on Bottom Layer "Q200_Bot" (solid, remove dead copper, pour order 11): 27.4,42.6 30.5,39.5 30.5,37 31,36.5 38.5,36.5 38.5,55 25,55 12.5,55 12.5,42.6
N20143236 on Bottom Layer "Q203_Bot" (solid, remove dead copper, pour order 17): 33,31 23,31 23,5 30.5,5 30.5,23.1 32.2,24.8 38.5,24.8 38.5,36.392 33,36.392
N20143215 on Bottom Layer "Q202_Bot" (solid, remove dead copper, pour order 13): 9.5,42.5 9.5,37.2 25,37.2 25,31 33,31 33,37.5 28,42.5
GND on Bottom Layer "GND_L1" (solid, remove dead copper, pour order 24): 0,0 0,56 38.5,56 38.5,0
N20143236 on Top Layer "Q203_Top" (solid, remove dead copper, pour order 8): 26,31 26,24 27.5,24 27.5,20 30,20 31,21 31,24 33.5,24 35,25.5 35,30 34,31
N20143229 on Top Layer "Q200_Top" (solid, remove dead copper, pour order 7): 38.5,30 36.55,30 36.55,37.55 36.55,55.237 38.5,55.237
N20143215 on Top Layer "Q202_Top" (solid, remove dead copper, pour order 9): 6,42.5 6,34 16,34 21.5,39.5 22,39.5 22,42.5
N20143311 on Top Layer "Q201_Top" (solid, remove dead copper, pour order 10): 25,19.5 25,15.5 20.628,15.5 20.628,21 12.5,21 12.5,5 20.5,5 27,11.5 29.5,11.5 29.5,16.5 34.5,22 36.4,22 36.4,0.5 38.5,0.5 38.5,24 38.5,30 35,30 35,25.8 33.4,24.2 31.5,24.2 31.5,21 30,19.5
GND on Top Layer "GND_L4" (solid, remove dead copper, pour order 23): 0,0 0,56 38.5,56 38.5,0

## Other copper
Top Layer:
  rectangle net GND: 20.5,53.5 24.5,54.5
  region net N20143236: 31,21.5 30,21.5 30,20 27.5,20 27.5,24.2 29.4,24.2 29.4,28.4 34.1,28.4 34.1,24.8 33.55,24.25 30.6,24.25 30.6,23.6 31,23.2
  region net N20297522: 17.3,53 17.3,46.8 12.5,42 12.5,40.7 16.6,40.7 20.5,44.6 20.5,48.5 21.9,49.9 29.5,49.9 29.5,53
  region net GND: 27,39.4 25.5,39.4 25.5,37.5 27,37.5
  region net GND: 35.5,48.5 34,50 31,50 31,54.925 36.075,54.925 37,54 37,40.5 35.5,40.5
  region net GND: 35.5,19.5 37,19.5 37,13.5 35.5,13.5
  region net GND: 27,24.2 26.3,24.2 25.8,23.7 25.8,22.7 26.1,22.7 26.1,21.5 27,21.5
  region net USBC_VBUS: 33.7,12.8 30.3,12.8 29,11.5 27,11.5 26,10.5 26,8.5 27,8.5 28,9.5 28.5,9.5 28.5,11 31,11 31.5,11.5 32,11.5 32.5,11 33.7,11
  region net N20143267: 33,19.5 35,21.5 36.5,21.5 36.5,20 35,20 35,13 37,13 37,11 34.5,11 34.5,12.5 34,13 29.5,13 29.5,16 33,16
  region net N20143215: 33,31.1 33,35 32.5,35.5 29.2,35.5 29.2,36.6 29.994,36.6 29.994,37.5 31,37.5 31,39 27.5,42.5 21.5,42.5 21.5,39.55 27.5,39.55 27.5,36.6 26.1,36.6 26.1,33.3 26.1,31.5 26.5,31.1
  region net VIN: 35,40 36.3,40 36.3,38.4 34,38.4 34,39.6 33.8,39.8 33.8,43.8 29.5,43.8 26.8,46.5 21,46.5 21,48 22.5,49.5 33.5,49.5 35,48
  region net N20143229: 31.5,39 27,43.5 27,45.5 27.5,45.5 29.35,43.65 33.65,43.65 33.65,39.545 33.8,39.395 33.8,37.6 37,37.6 37,30 34,30 34,35.5 33.5,36 31.5,36
  region net GND: 22.2,46.1 22.2,45 21.5,45 21.5,42.9 26.5,42.9 26.5,46.1
  region net N20143311: 31.5,24 31.5,20.9 30.1,19.5 29,19.5 27,17.5 27,14 27,12.5 29,12.5 29,16.5 32.5,16.5 32.5,19.5 34,21 34,22.4 37,22.4 37,24.5 37,29.5 35.5,29.5 35.5,24.5 34,24.5 33.5,24
  region net GND: 22.9,16.7 22.9,14 26.5,14 26.5,17.05 23.25,17.05
Signal Layer 2:
  region net N20143215: 27,39.5 29.5,39.5 29.5,36.5 27,36.5
  region net N20143311: 31,23.3 31.7,23.8 33.5,23.8 33.5,20.1 31,20.1
  region net N20143236: 27,23.5 29.5,23.5 29.5,20.5 27,20.5
  region net N20143229: 31,39.5 33.5,39.5 33.5,36.5 31.5,36.5 31.5,37 31,37
Signal Layer 3:
  region net N20143311: 31,23.25 33.5,23.25 33.5,19.85 31,19.85
  region net N20143236: 27,24.15 29.5,24.15 29.5,20.65 27,20.65
  region net N20143215: 27,39.5 29.5,39.5 29.5,36.5 27,36.5
  region net N20143229: 31,39.5 33.5,39.5 33.5,36.5 31.5,36.5 31.5,37 31,37
Bottom Layer:
  region net N20143311: 31,22.4 33.5,22.4 33.5,20.5 31,20.5
  region net N20143236: 27,23.5 28.3,23.5 28.65,23.15 29.5,23.15 29.5,20.5 27,20.5
  region net N20143215: 27,39.5 29.5,39.5 29.5,36.5 27,36.5
  region net N20143229: 31,39.5 33.5,39.5 33.5,36.5 31.5,36.5 31.5,37 31,37

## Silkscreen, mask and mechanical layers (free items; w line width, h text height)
Top Overlay:
  text "+" at 23.8,52.7 h3.3 r270
  text "-" at 35.8,52.4 h3.3 r270
  text "VBAT" at 0.6,50.512 h1.25 r270
  text "5V" at 5.75,50.362 h1.25 r270
  text "VBUS" at 5.75,48.712 h1.25 r270
  text "NC" at 0.6,47.212 h1.25 r270
  text "VDD" at 5.75,45.412 h1.25 r270
  text "P0.2" at 0.6,45.162 h1.25 r270
  text "P2.0" at 5.75,42.762 h1.25 r270
  text "P0.3" at 0.6,42.712 h1.25 r270
  text "P2.1" at 5.75,40.312 h1.25 r270
  text "P0.4" at 0.6,40.212 h1.25 r270
  text "12V" at 15.2,39.9 h2.5 r270
  text "P2.2" at 5.75,37.712 h1.25 r270
  text "P0.5" at 0.6,37.662 h1.25 r270
  text "P2.3" at 5.75,35.162 h1.25 r270
  text "P0.6" at 0.6,35.112 h1.25 r270
  text "P2.4" at 5.75,32.712 h1.25 r270
  text "P0.7" at 0.6,32.612 h1.25 r270
  text "P2.5" at 5.75,30.112 h1.25 r270
  text "P1.0" at 0.6,30.062 h1.25 r270
  text "P2.6" at 5.75,27.512 h1.25 r270
  text "P1.1" at 0.6,27.462 h1.25 r270
  text "EFM8BB3" at 18.4,25.9 h1.6 r270
  text "P3.0" at 5.75,25.062 h1.25 r270
  text "P1.2" at 0.6,24.962 h1.25 r270
  text "P3.1" at 5.75,22.462 h1.25 r270
  text "P1.3" at 0.6,22.412 h1.25 r270
  text "P3.2" at 5.75,19.912 h1.25 r270
  text "P1.4" at 0.6,19.862 h1.25 r270
  text "LED1" at 18.4,18 h1.2 r270
  text "P3.3" at 5.75,17.462 h1.25 r270
  text "P1.5" at 0.6,17.362 h1.25 r270
  text "LED0" at 18.4,15.1 h1.2 r270
  text "P3.4" at 5.75,14.862 h1.25 r270
  text "P1.6" at 0.6,14.812 h1.25 r270
  text "RESET" at 12.7,13.8 h1.25 r270
  text "P1.7" at 0.6,12.312 h1.25 r270
  text "CT" at 5.75,11.962 h1.25 r270
  text "USB Type-C PD" at 18.4,11.2 h1.6 r270
  text "GND" at 0.6,9.912 h1.25 r270
  text "GND" at 5.75,9.912 h1.25 r270
  text "C2CK" at 0.6,7.312 h1.25 r270
  text "C2D" at 5.75,7.162 h1.25 r270
  text "J-LINK" at 5.7,4.1 h1.25 r270
Bottom Overlay:
  circle w0.152: c3,2 r0.966
  text "+" at 23.8,52.7 h3.3 r270
  text "-" at 35.8,52.4 h3.3 r270
  text "PCB5204A Rev A03" at 36,9 h1.25 r270
Top Solder:
  the board outline again, w1
Bottom Solder:
  the board outline again, w1
BOARD OUTLINE 1:
  lines w0.1: 0,1.2 ccw(c-1.2,1.2) -2.4,1.2 ccw(c1.2,1.2) 1.2,-2.4 37.3,-2.4 ccw(c37.3,1.2) 40.9,1.2 ccw(c39.7,1.2) 38.5,1.2 ; 0,1.2 ccw(c1.2,1.2) 1.2,0 37.3,0 ccw(c37.3,1.2) 38.5,1.2 ; 0,1.2 0,54.3 ; 0,54.3 cw(c-1.2,54.3) -2.4,54.3 cw(c1.2,54.3) 1.2,57.9 37.3,57.9 cw(c37.3,54.3) 40.9,54.3 cw(c39.7,54.3) 38.5,54.3 ; 0,54.3 cw(c1.2,54.3) 1.2,55.5 37.3,55.5 cw(c37.3,54.3) 38.5,54.3 ; 38.5,1.2 38.5,54.3
Mechanical 4:
  drawing of 251 lines, arcs and shapes, not listed
Mechanical 26:
  lines w0.2: -113.935,-42.031 -108.935,-42.031 ; -113.935,4.969 -108.935,4.969 ; -113.923,51.969 -108.935,51.969 ; -42.728,-89.062 -42.728,-84.062 ; -42.728,95.938 -42.728,100.938 ; 28.572,-89.062 28.572,-84.062 ; 28.572,95.938 28.572,100.938 ; 99.772,-89.062 99.772,-84.062 ; 99.772,95.938 99.772,100.938 ; 166.065,-42.031 171.065,-42.031 ; 166.065,4.969 171.065,4.969 ; 166.065,51.969 171.053,51.969 ; -113.923,-89.062 171.065,-89.062 171.065,100.93 -113.923,100.93 -113.923,-89.062 ; -108.935,-84.062 166.065,-84.062 166.065,95.938 -108.935,95.938 -108.935,-84.062
  text "1" at -81.035,97.51 h1.52
  text "2" at -8.728,97.51 h1.52
  text "3" at 63.872,97.51 h1.52
  text "4" at 134.672,97.51 h1.52
  text "D" at 168.063,78.369 h1.52
  text "D" at -112.048,77.164 h1.52
  text "C" at -112.048,29.669 h1.52
  text "C" at 167.936,29.669 h1.52
  text "B" at -112.048,-17.931 h1.52
  text "B" at 167.936,-17.931 h1.52
  text "A" at -112.048,-65.431 h1.52
  text "A" at 167.936,-65.431 h1.52
  text "1" at -79.816,-87.504 h1.52
  text "2" at -8.728,-87.504 h1.52
  text "3" at 63.572,-87.504 h1.52
  text "4" at 134.272,-87.504 h1.52
Mechanical 27:
  circle w0.254: c50.093,-77.064 r2.962
  circle w0.152: c82.077,-62.607 r1.778
  circle w0.152: c82.077,-62.607 r0.762
  lines w0.152: 71.079,-62.607 78.445,-62.607 ; 79.791,-62.607 84.363,-62.607 ; 71.841,-63.369 71.841,-61.845 77.683,-60.829 77.658,-64.385 71.841,-63.369
  lines w0.2: 46.044,-83.998 46.044,-57.138 86.058,-57.138 ; 46.044,-69.774 166.009,-69.774 ; 46.058,-66.138 86.058,-66.138 ; 66.339,-83.947 66.339,-69.85 ; 66.339,-66.091 66.339,-57.175 ; 146.058,-69.748 146.058,-66.138 ; 156.058,-66.138 156.058,-57.138 ; 166.058,-66.138 86.058,-66.138 ; 166.058,-57.138 86.058,-57.138 ; 86.058,-66.138 86.058,-57.138
  text "SIZE" at 48.058,-59.138 h1.52
  text "DOC NO" at 88.058,-59.138 h1.52
  text "REV" at 158.058,-59.138 h1.52
  text "PROJECTION" at 67.355,-59.487 h1.52
  text "A03" at 157.779,-64.059 h2.54
  text "A4" at 50.708,-64.512 h2.54
  text "BRD5204" at 88.38,-64.5 h2.54
  text "REF" at 48.058,-68.138 h1.52
  text "SHEET" at 147.058,-68.138 h1.52
  text "1 of 2" at 156.9,-69.175 h1.52
  text "This drawing is confidential and is supplied on the express" at 66.822,-72.746 h1.52
  text "condition that it shall not be loaned, copied or disclosed to any" at 66.822,-75.286 h1.52
  text "other person or used for any purpose without the written consent of" at 66.822,-77.826 h1.52
  text "C" at 49.499,-78.08 h2.03
  text "2016" at 54.579,-78.232 h2.54
  text "SILICON LABS" at 67.253,-82.118 h2.54
Mechanical 28:
  lines w0.2: -113.859,-42.107 -108.859,-42.107 ; -113.859,4.893 -108.859,4.893 ; -113.847,51.893 -108.859,51.893 ; 166.141,-42.107 171.141,-42.107 ; 166.141,51.893 171.141,51.893
  lines w0.203: -42.651,-89.138 -42.651,-84.138 ; -42.651,95.862 -42.651,100.862 ; 28.649,-89.138 28.649,-84.138 ; 28.649,95.862 28.649,100.862 ; 99.849,-89.138 99.849,-84.138 ; 99.849,95.862 99.849,100.862 ; -113.925,-89.05 -113.925,100.925 171.05,100.925 171.05,-89.05 -113.925,-89.05 ; -108.925,-84.075 -108.925,95.925 166.075,95.925 166.075,-84.075 -108.925,-84.075
  text "4" at -79.943,97.433 h1.52
  text "3" at -7.635,97.433 h1.52
  text "2" at 64.965,97.433 h1.52
  text "1" at 135.765,97.433 h1.52
  text "D" at 169.155,78.293 h1.52
  text "D" at -110.956,77.088 h1.52
  text "C" at -110.956,29.593 h1.52
  text "C" at 169.155,27.993 h1.52
  text "B" at -110.956,-18.007 h1.52
  text "B" at 169.155,-19.107 h1.52
  text "A" at 168.137,-65.431 h1.52
  text "A" at -110.956,-65.507 h1.52
  text "A" at 169.028,-65.507 h1.52
  text "4" at -78.723,-87.58 h1.52
  text "3" at -7.635,-87.58 h1.52
  text "2" at 64.512,-87.58 h1.52
  text "1" at 135.365,-87.58 h1.52
Mechanical 29:
  circle w0.254: c7.204,-77.128 r2.962
  circle w0.152: c-24.781,-62.671 r1.778
  circle w0.152: c-24.781,-62.671 r0.762
  lines w0.152: -27.067,-62.671 -22.495,-62.671 ; -21.149,-62.671 -13.783,-62.671 ; -20.387,-60.893 -14.545,-61.909 -14.545,-63.433 -20.361,-64.449 -20.387,-60.893
  lines w0.2: -108.762,-66.202 -28.762,-66.202 ; -108.762,-57.202 -28.762,-57.202 ; -108.712,-69.838 11.252,-69.838 ; -98.762,-66.202 -98.762,-57.202 ; -88.762,-69.813 -88.762,-66.202 ; -9.043,-84.011 -9.043,-69.914 ; -9.043,-66.155 -9.043,-57.24 ; 11.238,-66.202 -28.762,-66.202 ; 11.238,-57.202 -28.762,-57.202 ; 11.252,-84.062 11.252,-57.138 ; -28.762,-66.202 -28.762,-57.202
  text "REV" at -100.762,-59.202 h1.52
  text "DOC NO" at -30.762,-59.202 h1.52
  text "SIZE" at 9.238,-59.202 h1.52
  text "PROJECTION" at -10.059,-59.551 h1.52
  text "A03" at -100.483,-64.123 h2.54
  text "BRD5204" at -30.9,-64.4 h2.54
  text "A4" at 6.588,-64.576 h2.54
  text "SHEET" at -89.762,-68.202 h1.52
  text "REF" at 9.238,-68.202 h1.52
  text "2 of 2" at -99.45,-69.175 h1.52
  text "This drawing is confidential and is supplied on the express" at -9.525,-72.81 h1.52
  text "condition that it shall not be loaned, copied or disclosed to any" at -9.525,-75.35 h1.52
  text "other person or used for any purpose without the written consent of" at -9.525,-77.89 h1.52
  text "C" at 7.798,-78.144 h2.03
  text "2016" at 2.718,-78.296 h2.54
  text "SILICON LABS" at -9.957,-82.182 h2.54
Mechanical 30:
  lines w0.2: 46.044,-57.138 46.044,-36.298 166.044,-36.298 ; 46.044,-53.202 86.044,-53.202 ; 46.044,-49.202 86.044,-49.202 ; 46.044,-45.202 86.044,-45.202 ; 86.044,-49.203 166.044,-49.203 ; 86.044,-41.202 166.044,-41.202 ; 86.051,-57.138 86.051,-36.298
  text "CUSTOMER" at 87.153,-38.215 h1.27
  text "PROJECT NO" at 47.529,-39.231 h1.52
  text "SILICON LABS" at 104.933,-39.739 h2.03
  text "DRAWING TITLE" at 87.382,-43.143 h1.52
  text "BRD5204A" at 48.799,-43.676 h3.3
  text "DATE" at 47.529,-47.359 h1.52
  text "EFM8UB3 USB Type-C Battery Pack" at 90.557,-47.406 h2.03
  text "'.Print_Date'" at 65.817,-48.375 h1.52
  text "SHEET NAME" at 87.178,-51.296 h1.52
  text "DRAWN" at 47.529,-51.423 h1.52
  text "CHECK" at 47.529,-55.487 h1.52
